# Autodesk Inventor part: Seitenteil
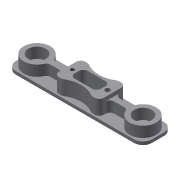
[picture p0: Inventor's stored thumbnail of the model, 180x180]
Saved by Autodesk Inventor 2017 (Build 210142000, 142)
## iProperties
Created: 2015-04
Part Number: Seitenteil
Material: Generisch
Document SubType Name: Modeling
Designer: e_krauts
Density: 1 g/cm^3
Appearance: Vorgabe
Mass: 43.9559 g
Surface Area: 202.761 cm^2
Volume: 43.9559 cm^3
Author: e_krauts
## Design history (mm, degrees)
sketch "Skizze1"
  geometry: L1 (0, 0)-(154, 0); L2 (154, 0)-(154, 34); L3 (154, 34)-(0, 34); L4 (0, 34)-(0, 0)
  constraints: 8 end point, 2 parallel, 1 horizontal, 1 perpendicular
  dimensions: "d0" = 154 distance of L3.end L2.end; "d1" = 34 distance between parallel lines of L3 L1
extrude "Extrusion1" new body sketch "Skizze1" distance "d2" = 3.5; taper "d3" = 0 deg
sketch "Skizze2"
  geometry: L1 (0, 0)-(154, 0) reference; L2 (154, 0)-(154, 34) reference; L3 (154, 34)-(0, 34) reference; L4 (0, 34)-(0, 0) reference; L5 (77, 34)-(77, 0); L6 (0, 17)-(154, 17); L7 (77, 20)-(35.33, 20); L8 (77, 14)-(35.33, 14); L9 (77, 20)-(118.67, 20); L10 (77, 14)-(118.67, 14); L11 (154, 17)-(0, 17); A1 r 5 centre (35.33, 25) between (30.748, 23) and (35.33, 20); A2 r 15 centre (17, 17) between (30.748, 23) and (2, 17); A3 r 5 centre (35.33, 9) between (35.33, 14) and (30.748, 11); A4 r 15 centre (17, 17) between (2, 17) and (30.748, 11); A5 r 5 centre (118.67, 25) between (118.67, 20) and (123.252, 23); A6 r 15 centre (137, 17) between (123.252, 11) and (152, 17); A7 r 15 centre (137, 17) between (152, 17) and (123.252, 23); A8 r 5 centre (118.67, 9) between (123.252, 11) and (118.67, 14)
  constraints: 16 point on circle, 14 end point, 14 symmetric about line, 8 centre point, 5 point on line, 4 midpoint, 2 tangent, 1 parallel, 6 other
  dimensions: "d4" = 6 diameter of L7 L6; "d5" = 15 radius of A2; "d6" = 120 diameter of A2.centre L5; "d7" = 5 radius of A1
extrude "Extrusion2" join sketch "Skizze2" distance "d8" = 12; taper "d9" = 0 deg
sketch "Skizze3"
  geometry: A1 r 15 centre (17, 17) between (30.748, 23) and (30.748, 11) reference; A2 r 15 centre (137, 17) between (123.252, 11) and (123.252, 23) reference; 3 further points
  constraints: 2 coincident
hole "Bohrung1" sketch "Skizze3" at (17, 17), (137, 17) diameter "d10" = 20; stored, may be unused: countersink angle "d14" = 90 deg, drill point angle "d16" = 0 deg; dims "d11" = 6, "d12" = 4, "d13" = 2, "d15" = 12
fillet "Rundung1" dims "d17" = 10
sketch "Skizze4"
  geometry: L1 (144, 34)-(10, 34) reference; L2 (0, 24)-(0, 10) reference; L3 (10, 0)-(144, 0) reference; L4 (154, 10)-(154, 24) reference; L5 (77, 34)-(77, 0); L6 (0, 17)-(154, 17); L7 (102.5, 32)-(51.5, 32); L8 (51.5, 32)-(51.5, 2); L9 (51.5, 2)-(102.5, 2); L10 (102.5, 2)-(102.5, 32); L11 (102.5, 32)-(51.5, 2); L12 (51.5, 32)-(102.5, 2); 2 further points
  constraints: 16 end point, 7 midpoint, 2 parallel, 1 horizontal, 1 perpendicular
  dimensions: "d18" = 51 distance of L9.end L8.end; "d19" = 30 distance of L8.end L7.end
extrude "Extrusion3" join sketch "Skizze4" distance "d20" = 16.5; taper "d21" = 0 deg
fillet "Rundung2" dims "d22" = 5
sketch "Skizze5"
  geometry: L1 (62, 24.5)-(92, 24.5); L2 (92, 24.5)-(92, 9.5); L3 (92, 9.5)-(62, 9.5); L4 (62, 9.5)-(62, 24.5); L5 (62, 24.5)-(92, 9.5); L6 (92, 24.5)-(62, 9.5); 2 further points
  constraints: 12 end point, 2 midpoint, 2 parallel, 1 horizontal, 1 perpendicular
  dimensions: "d23" = 30 distance of L2.end L3.end; "d24" = 15 distance of L1.end L2.end
extrude "Extrusion4" cut sketch "Skizze5" distance "d25" = 16.5; taper "d26" = 0 deg
fillet "Rundung3" dims "d27" = 5
sketch "Skizze6"
  geometry: L1 (51.5, 27)-(51.5, 7) reference; L2 (56.5, 2)-(97.5, 2) reference; L3 (102.5, 7)-(102.5, 27) reference; L4 (97.5, 32)-(56.5, 32) reference; L5 (51.5, 17)-(102.5, 17); L6 (77, 32)-(77, 2); L7 (60.417, 32)-(93.583, 32); L8 (60.417, 2)-(93.583, 2); A1 r 30 centre (77, 57) between (60.417, 32) and (93.583, 32); A2 r 30 centre (77, -23) between (93.583, 2) and (60.417, 2); 1 further point
  constraints: 8 end point, 4 midpoint, 4 point on circle, 3 symmetric about line, 2 centre point, 2 point on line, 1 collinear, 1 other
  dimensions: "d30" = 80 diameter of A1.centre L5; "d31" = 30 radius of A1
extrude "Extrusion5" cut sketch "Skizze6" distance "d32" = 16.5; taper "d33" = 0 deg
fillet "Rundung4" dims "d34" = 5
sketch "Skizze7"
  geometry: L1 (51.5, 27)-(51.5, 7) reference; L2 (102.5, 7)-(102.5, 27) reference; L3 (51.5, 17)-(102.5, 17); L4 (77, 27)-(77, 7); A1 r 30 centre (77, -23) between (92.452, 2.714) and (61.548, 2.714) reference; A2 r 30 centre (77, 57) between (61.548, 31.286) and (92.452, 31.286) reference; 3 further points
  constraints: 4 end point, 2 midpoint, 2 point on circle, 1 point on line, 1 symmetric about line
hole "Bohrung2" sketch "Skizze7" diameter "d36" = 4.134; stored, may be unused: countersink angle "d40" = 90 deg, drill point angle "d42" = 118 deg; dims "d37" = 14, "d38" = 4, "d39" = 2, "d41" = 17
sketch "Skizze9"
  geometry: C1 r 5.2 at (0, 0) reference; 2 further points
  constraints: 1 coincident
hole "Bohrung4" sketch "Skizze9" diameter "d61" = 5.5; stored, may be unused: countersink angle "d65" = 90 deg, drill point angle "d67" = 118 deg; dims "d62" = 6, "d63" = 10.4, "d64" = 2, "d66" = 8
node "Volumenkörper1"
hole "Bohrung3" diameter "d54" = 10.4; stored, may be unused: countersink angle "d58" = 90 deg, drill point angle "d60" = 0 deg; dims "d52" = 17, "d53" = 57, "d55" = 6, "d56" = 4, "d57" = 2, "d59" = 0.5
